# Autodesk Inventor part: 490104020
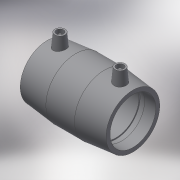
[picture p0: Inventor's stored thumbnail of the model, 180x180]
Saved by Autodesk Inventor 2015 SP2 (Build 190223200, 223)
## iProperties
Created: 2017-06
Part Number: 490104020
Material: Generic
Description: PLASSON COUPLER 20-20
Document SubType Name: Modeling
Designer: KIM
Mass: 35.4395 g
Surface Area: 157.975 cm^2
Volume: 35.4395 cm^3
Density: 1 g/cm^3
Appearance: Default
Author: KIM
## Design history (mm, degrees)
derived "490104.ipt"
feature "Solid1::490104.ipt"
tag "TaggingFeature1"
body "Solid1"
other parameters: "d0" = 76, "d2" = 31, "d3" = 37, "d4" = 25.33333, "d5" = 27.9, "d6" = 19, "d8" = 168 deg, "d10" = 14.8, "d11" = 4.93333, "d13" = 76, "d14" = 17.6296, "d15" = 37, "d16" = 37, "d17" = 19, "d19" = 3.52592, "d20" = 168 deg, "d22" = 29.14, "d23" = 31, "d24" = 28.2658, "d25" = 135 deg, "d26" = 30.4, "d27" = 135 deg, "d29" = 34, "d30" = 14, "d31" = 26.6, "d34" = 5 deg, "d35" = 15, "d39" = 5 deg, "d41" = 4, "d42" = 14, "d43" = 0, "d45" = 4, "d46" = 14, "d47" = 0, "d48" = 3, "d49" = 0, "d50" = 3, "d51" = 0, "d52" = 10.73, "d53" = 2.6825, "L_" = 76, "L_1" = 37, "D_" = 31, "A_" = 34, "d_2" = 12
